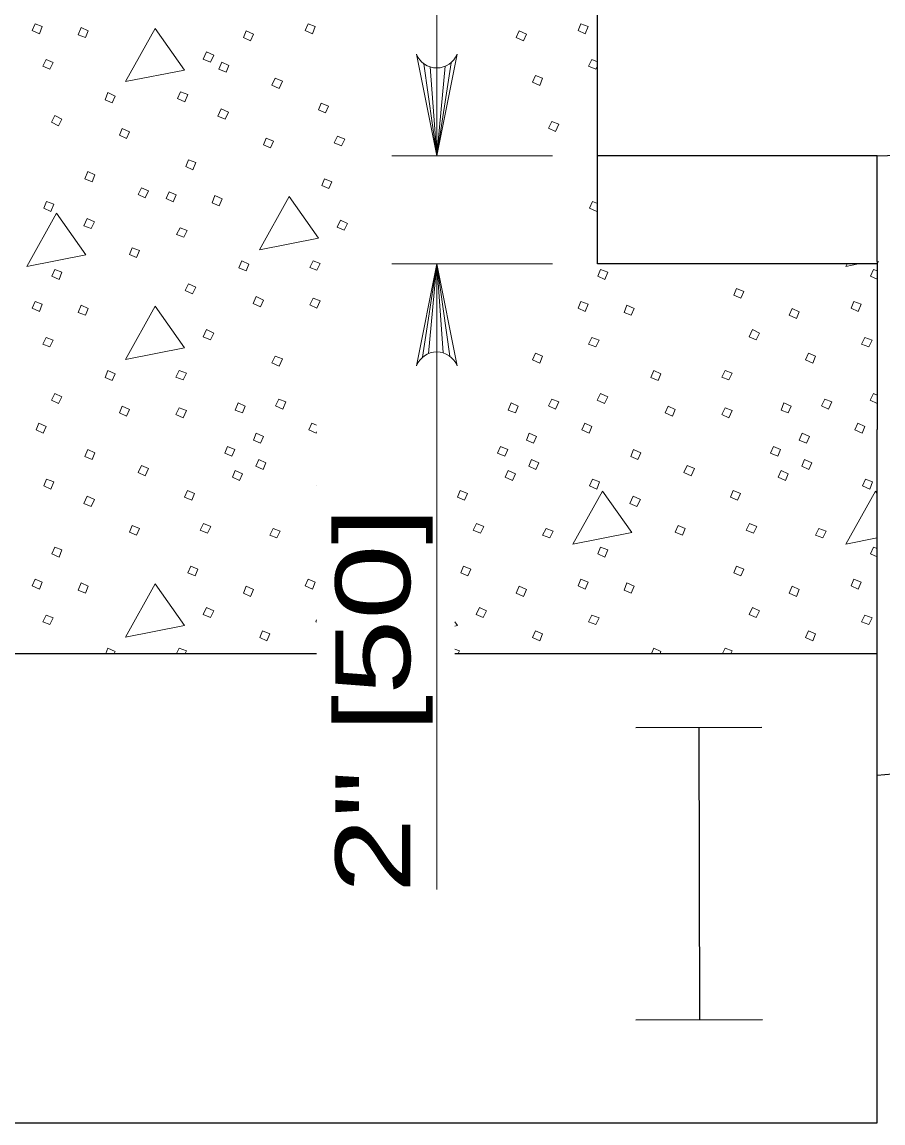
# Model space of a CAD drawing. Extents: x 1083.1 to 1123, y 697.4 to 741.4.
# Drawn here: x 1091.084 to 1092.878, y 711.561 to 713.855 of the extents above; entities that cross this region are included whole.
import ezdxf

# ---------------------------------------------------------------- set-up
doc = ezdxf.new("R2010")
doc.units = 0
doc.header["$LTSCALE"] = 0.062
doc.layers.add('1', color=7, linetype='Continuous', lineweight=13)

msp = doc.modelspace()

# ---------------------------------------------------------------- linework, layer by layer
at = {"layer": '1'}
for p, q in [((1091.94833, 713.92525), (1091.94833, 713.57625)), ((1091.9215, 713.76825), (1091.94833, 713.57625)), ((1091.93475, 713.76175), (1091.94833, 713.57625)), ((1091.978, 713.7705), (1091.94833, 713.57625)), ((1091.96558, 713.76317), (1091.94833, 713.57625)), ((1091.94833, 713.75975), (1091.94833, 713.57625)), ((1092.27175, 713.777), (1092.28325, 713.77242)), ((1092.18967, 713.57625), (1091.85475, 713.57625)), ((1092.27275, 713.48167), (1092.28325, 713.4775)), ((1092.18967, 713.35117), (1091.85475, 713.35117)), ((1091.91867, 713.157), (1091.94833, 713.35117)), ((1091.93108, 713.16433), (1091.94833, 713.35117)), ((1091.94833, 713.16417), (1091.94833, 713.35117)), ((1091.94833, 713.16775), (1091.94833, 713.35117)), ((1091.96192, 713.16575), (1091.94833, 713.35117)), ((1091.97517, 713.15925), (1091.94833, 713.35117)), ((1092.86625, 713.3535), (1092.869, 713.35617)), ((1092.85842, 713.34), (1092.86625, 713.33683)), ((1092.85842, 713.08158), (1092.86625, 713.07792)), ((1091.688, 713.01975), (1091.698, 713.01508)), ((1092.86625, 712.8725), (1092.86242, 712.87808)), ((1092.85842, 712.76133), (1092.86625, 712.75817)), ((1091.25833, 712.53942), (1091.26292, 712.55083)), ((1091.40592, 712.53942), (1091.41158, 712.55083)), ((1092.39583, 712.53942), (1092.40042, 712.55083)), ((1092.54342, 712.53942), (1092.54908, 712.55083))]:
    msp.add_line(p, q, dxfattribs=at)
at = {"layer": '1', "lineweight": 25}
for p, q in [((1092.86625, 713.57625), (1094.211, 713.62042)), ((1092.86625, 713.57625), (1092.28325, 713.57625)), ((1092.86625, 713.356), (1092.86625, 713.57625)), ((1092.86625, 713.356), (1092.86625, 713.0065)), ((1092.86625, 712.53942), (1092.86625, 713.0065)), ((1088.68575, 712.53942), (1091.698, 712.53942)), ((1091.98583, 712.53942), (1092.86625, 712.53942)), ((1092.86625, 711.56133), (1092.86625, 712.53942)), ((1092.86625, 712.28617), (1095.26192, 712.49675)), ((1092.36333, 712.38567), (1092.6255, 712.38633)), ((1092.49442, 712.38608), (1092.496, 711.77658)), ((1092.36333, 711.77625), (1092.62708, 711.777)), ((1088.68575, 711.56133), (1092.86625, 711.56133))]:
    msp.add_line(p, q, dxfattribs=at)
for points in [[(1092.86625, 713.35117), (1092.28325, 713.35117), (1092.28325, 713.89792), (1091.6065, 714.96742), (1091.41967, 716.86658)], [(1092.28325, 713.646), (1092.28267, 713.64633), (1092.28325, 713.6475)]]:
    msp.add_lwpolyline(points, dxfattribs=at)
at = {"layer": '1'}
for points in [[(1091.11133, 713.85183), (1091.12625, 713.84583), (1091.12025, 713.83083), (1091.10533, 713.83783)], [(1091.68, 713.85183), (1091.695, 713.84583), (1091.689, 713.83083), (1091.674, 713.83783)], [(1092.24875, 713.85183), (1092.26375, 713.84583), (1092.25775, 713.83083), (1092.24275, 713.83783)], [(1091.20708, 713.84383), (1091.22208, 713.83683), (1091.21608, 713.82292), (1091.20108, 713.82892)], [(1091.36175, 713.84183), (1091.29983, 713.73108), (1091.42258, 713.75508)], [(1091.55133, 713.83683), (1091.56625, 713.82983), (1091.56033, 713.81592), (1091.54533, 713.82292)], [(1092.12008, 713.83683), (1092.135, 713.82983), (1092.129, 713.81592), (1092.11408, 713.82292)], [(1091.4685, 713.793), (1091.4835, 713.786), (1091.4765, 713.772), (1091.4615, 713.778)], [(1091.13425, 713.777), (1091.14917, 713.771), (1091.14225, 713.75708), (1091.12725, 713.763)], [(1091.50008, 713.772), (1091.51508, 713.765), (1091.50908, 713.751), (1091.49408, 713.757)], [(1091.61183, 713.73808), (1091.62683, 713.73208), (1091.61983, 713.71708), (1091.60483, 713.72408)], [(1092.154, 713.74408), (1092.16892, 713.73808), (1092.16292, 713.72308), (1092.148, 713.73008)], [(1091.41425, 713.71008), (1091.42925, 713.70417), (1091.42325, 713.68917), (1091.40825, 713.69617)], [(1091.26292, 713.70817), (1091.27792, 713.70117), (1091.27192, 713.68717), (1091.257, 713.69317)], [(1091.49908, 713.67417), (1091.51408, 713.66725), (1091.50708, 713.65325), (1091.49208, 713.65925)], [(1091.70758, 713.68617), (1091.72258, 713.68017), (1091.71658, 713.66617), (1091.70167, 713.67217)], [(1091.15217, 713.66025), (1091.16717, 713.65325), (1091.16017, 713.63933), (1091.14525, 713.64633)], [(1092.18792, 713.64833), (1092.20283, 713.64233), (1092.19592, 713.62733), (1092.18092, 713.63433)], [(1091.29292, 713.63333), (1091.30783, 713.62633), (1091.30183, 713.61242), (1091.28692, 713.61933)], [(1091.59283, 713.61333), (1091.60783, 713.60733), (1091.60183, 713.59342), (1091.58692, 713.59933)], [(1091.74158, 713.61733), (1091.7565, 713.61133), (1091.7495, 713.59733), (1091.73458, 713.60333)], [(1091.43125, 713.56842), (1091.44617, 713.56242), (1091.44017, 713.5475), (1091.42525, 713.5545)], [(1091.22108, 713.54358), (1091.236, 713.53658), (1091.23, 713.52258), (1091.21508, 713.52858)], [(1091.71458, 713.5285), (1091.72958, 713.5225), (1091.72358, 713.50858), (1091.70858, 713.51458)], [(1091.33283, 713.50958), (1091.34775, 713.50367), (1091.34075, 713.48867), (1091.32583, 713.49567)], [(1091.13525, 713.48167), (1091.15017, 713.47567), (1091.14425, 713.46075), (1091.12925, 713.46775)], [(1091.39033, 713.50158), (1091.40525, 713.49558), (1091.39933, 713.48067), (1091.38433, 713.48767)], [(1091.48608, 713.49358), (1091.50108, 713.48667), (1091.49508, 713.47267), (1091.48008, 713.47867)], [(1091.64075, 713.49158), (1091.57892, 713.38083), (1091.70167, 713.40483)], [(1091.15617, 713.45675), (1091.09433, 713.346), (1091.21708, 713.36992)], [(1091.22008, 713.44575), (1091.235, 713.43875), (1091.228, 713.42483), (1091.21308, 713.43083)], [(1091.7475, 713.44275), (1091.7625, 713.43575), (1091.7555, 713.42175), (1091.74058, 713.42775)], [(1091.41325, 713.42675), (1091.42825, 713.42075), (1091.42125, 713.40683), (1091.40625, 713.41283)], [(1091.31383, 713.38492), (1091.32883, 713.37892), (1091.32283, 713.36492), (1091.30783, 713.37092)], [(1091.542, 713.35792), (1091.55692, 713.35092), (1091.551, 713.337), (1091.536, 713.343)], [(1091.69067, 713.35792), (1091.70558, 713.35192), (1091.69867, 713.338), (1091.68367, 713.34392)], [(1091.15217, 713.34), (1091.16717, 713.334), (1091.16117, 713.31908), (1091.14625, 713.32608)], [(1092.28967, 713.34), (1092.30467, 713.334), (1092.29867, 713.31908), (1092.28367, 713.32608)], [(1091.43125, 713.31), (1091.44617, 713.30308), (1091.43925, 713.28908), (1091.42425, 713.29608)], [(1092.573, 713.30008), (1092.588, 713.29408), (1092.582, 713.28017), (1092.56708, 713.28617)], [(1091.57192, 713.28308), (1091.58692, 713.27608), (1091.58092, 713.26217), (1091.56592, 713.26917)], [(1091.69067, 713.28008), (1091.70558, 713.27417), (1091.69867, 713.25917), (1091.68367, 713.26617)], [(1091.11133, 713.27317), (1091.12625, 713.26717), (1091.12025, 713.25225), (1091.10533, 713.25917)], [(1091.20708, 713.26517), (1091.22208, 713.25825), (1091.21608, 713.24425), (1091.20108, 713.25025)], [(1091.36175, 713.26317), (1091.29983, 713.15242), (1091.42258, 713.17642)], [(1092.24875, 713.27317), (1092.26375, 713.26717), (1092.25775, 713.25225), (1092.24275, 713.25917)], [(1092.34458, 713.26517), (1092.3595, 713.25825), (1092.3535, 713.24425), (1092.33858, 713.25025)], [(1092.68875, 713.25825), (1092.70375, 713.25125), (1092.69775, 713.23725), (1092.68275, 713.24425)], [(1092.8175, 713.27317), (1092.8325, 713.26717), (1092.8265, 713.25225), (1092.8115, 713.25917)], [(1091.4685, 713.21433), (1091.4835, 713.20733), (1091.4765, 713.19333), (1091.4615, 713.19933)], [(1092.606, 713.21433), (1092.62092, 713.20733), (1092.61392, 713.19333), (1092.599, 713.19933)], [(1091.13425, 713.19833), (1091.14917, 713.19233), (1091.14225, 713.17842), (1091.12725, 713.18442)], [(1092.27175, 713.19833), (1092.28667, 713.19233), (1092.27967, 713.17842), (1092.26475, 713.18442)], [(1092.84042, 713.19833), (1092.85542, 713.19233), (1092.84842, 713.17842), (1092.8335, 713.18442)], [(1091.61183, 713.15942), (1091.62683, 713.15342), (1091.61983, 713.13842), (1091.60483, 713.14542)], [(1092.154, 713.16542), (1092.16892, 713.15942), (1092.16292, 713.1445), (1092.148, 713.1515)], [(1092.72267, 713.16542), (1092.73767, 713.15942), (1092.73167, 713.1445), (1092.71675, 713.1515)], [(1091.26292, 713.1295), (1091.27792, 713.1225), (1091.27192, 713.10858), (1091.257, 713.11458)], [(1091.41158, 713.1295), (1091.42658, 713.1235), (1091.41958, 713.10958), (1091.40467, 713.1155)], [(1092.40042, 713.1295), (1092.41542, 713.1225), (1092.40942, 713.10858), (1092.39442, 713.11458)], [(1092.54908, 713.1295), (1092.56408, 713.1235), (1092.55708, 713.10958), (1092.54208, 713.1155)], [(1091.15217, 713.08158), (1091.16717, 713.07467), (1091.16017, 713.06067), (1091.14525, 713.06767)], [(1091.61917, 713.06967), (1091.63408, 713.06367), (1091.62717, 713.04867), (1091.61217, 713.05567)], [(1092.18792, 713.06967), (1092.20283, 713.06367), (1092.19592, 713.04867), (1092.18092, 713.05567)], [(1092.28967, 713.08158), (1092.30467, 713.07467), (1092.29767, 713.06067), (1092.28267, 713.06767)], [(1092.75667, 713.06967), (1092.77158, 713.06367), (1092.76458, 713.04867), (1092.74967, 713.05567)], [(1091.29292, 713.05467), (1091.30783, 713.04767), (1091.30183, 713.03375), (1091.28692, 713.04075)], [(1091.41158, 713.05167), (1091.42658, 713.04567), (1091.41958, 713.03075), (1091.40467, 713.03775)], [(1091.53433, 713.06167), (1091.54933, 713.05467), (1091.54333, 713.04075), (1091.52833, 713.04667)], [(1092.10308, 713.06167), (1092.11808, 713.05467), (1092.11208, 713.04075), (1092.09708, 713.04667)], [(1092.43033, 713.05467), (1092.44533, 713.04767), (1092.43933, 713.03375), (1092.42433, 713.04075)], [(1092.54908, 713.05167), (1092.56408, 713.04567), (1092.55708, 713.03075), (1092.54208, 713.03775)], [(1092.67183, 713.06167), (1092.68675, 713.05467), (1092.68083, 713.04075), (1092.66583, 713.04667)], [(1091.11925, 713.01975), (1091.13425, 713.01275), (1091.12825, 712.99883), (1091.11325, 713.00583)], [(1091.57225, 712.99883), (1091.58725, 712.99183), (1091.58125, 712.97783), (1091.56625, 712.98383)], [(1092.141, 712.99883), (1092.156, 712.99183), (1092.15, 712.97783), (1092.135, 712.98383)], [(1092.25675, 713.01975), (1092.27175, 713.01275), (1092.26575, 712.99883), (1092.25075, 713.00583)], [(1092.70975, 712.99883), (1092.72467, 712.99183), (1092.71875, 712.97783), (1092.70375, 712.98383)], [(1092.8255, 713.01975), (1092.84042, 713.01275), (1092.83442, 712.99883), (1092.8195, 713.00583)], [(1091.22108, 712.96492), (1091.236, 712.95792), (1091.23, 712.94392), (1091.21508, 712.94992)], [(1091.51242, 712.97083), (1091.52733, 712.96492), (1091.52142, 712.95092), (1091.50642, 712.95692)], [(1092.08117, 712.97083), (1092.09608, 712.96492), (1092.09008, 712.95092), (1092.07517, 712.95692)], [(1092.3585, 712.96492), (1092.3735, 712.95792), (1092.3675, 712.94392), (1092.3525, 712.94992)], [(1092.64983, 712.97083), (1092.66483, 712.96492), (1092.65883, 712.95092), (1092.64392, 712.95692)], [(1091.33283, 712.931), (1091.34775, 712.925), (1091.34075, 712.91), (1091.32583, 712.917)], [(1091.57725, 712.94392), (1091.59225, 712.937), (1091.58625, 712.923), (1091.57125, 712.93)], [(1092.146, 712.94392), (1092.161, 712.937), (1092.155, 712.923), (1092.14, 712.93)], [(1092.47025, 712.931), (1092.48525, 712.925), (1092.47825, 712.91), (1092.46325, 712.917)], [(1092.71475, 712.94392), (1092.72967, 712.937), (1092.72375, 712.923), (1092.70875, 712.93)], [(1091.52833, 712.921), (1091.54333, 712.914), (1091.53733, 712.90008), (1091.52242, 712.907)], [(1092.09708, 712.921), (1092.11208, 712.914), (1092.10608, 712.90008), (1092.09108, 712.907)], [(1092.66583, 712.921), (1092.68083, 712.914), (1092.67483, 712.90008), (1092.65983, 712.907)], [(1091.13525, 712.903), (1091.15017, 712.89708), (1091.14425, 712.88208), (1091.12925, 712.88908)], [(1092.27275, 712.903), (1092.28767, 712.89708), (1092.28167, 712.88208), (1092.26675, 712.88908)], [(1092.84142, 712.903), (1092.85642, 712.89708), (1092.85042, 712.88208), (1092.83542, 712.88908)], [(1091.22008, 712.86708), (1091.235, 712.86017), (1091.228, 712.84617), (1091.21308, 712.85217)], [(1091.42858, 712.87908), (1091.44358, 712.87308), (1091.43758, 712.85917), (1091.42258, 712.86508)], [(1091.99733, 712.87908), (1092.01225, 712.87308), (1092.00633, 712.85917), (1091.99133, 712.86508)], [(1092.29367, 712.87808), (1092.23183, 712.76733), (1092.3545, 712.79133)], [(1092.3575, 712.86708), (1092.3725, 712.86017), (1092.3655, 712.84617), (1092.3505, 712.85217)], [(1092.56608, 712.87908), (1092.581, 712.87308), (1092.575, 712.85917), (1092.56008, 712.86508)], [(1091.31383, 712.80625), (1091.32883, 712.80025), (1091.32283, 712.78633), (1091.30783, 712.79233)], [(1091.4625, 712.81025), (1091.4775, 712.80425), (1091.4705, 712.79033), (1091.4555, 712.79625)], [(1091.60717, 712.80025), (1091.62217, 712.79425), (1091.61517, 712.78033), (1091.60017, 712.78633)], [(1092.03125, 712.81025), (1092.04625, 712.80425), (1092.03925, 712.79033), (1092.02425, 712.79625)], [(1092.17592, 712.80025), (1092.19092, 712.79425), (1092.18392, 712.78033), (1092.16892, 712.78633)], [(1092.45133, 712.80625), (1092.46625, 712.80025), (1092.46025, 712.78633), (1092.44533, 712.79233)], [(1092.6, 712.81025), (1092.61492, 712.80425), (1092.608, 712.79033), (1092.593, 712.79625)], [(1092.74467, 712.80025), (1092.75967, 712.79425), (1092.75267, 712.78033), (1092.73767, 712.78633)], [(1091.15217, 712.76133), (1091.16717, 712.75542), (1091.16117, 712.74042), (1091.14625, 712.74742)], [(1092.28967, 712.76133), (1092.30467, 712.75542), (1092.29867, 712.74042), (1092.28367, 712.74742)], [(1091.43558, 712.7215), (1091.4505, 712.7155), (1091.44458, 712.7015), (1091.42958, 712.7075)], [(1092.00433, 712.7215), (1092.01925, 712.7155), (1092.01325, 712.7015), (1091.99833, 712.7075)], [(1092.573, 712.7215), (1092.588, 712.7155), (1092.582, 712.7015), (1092.56708, 712.7075)], [(1091.11133, 712.6945), (1091.12625, 712.6885), (1091.12025, 712.67358), (1091.10533, 712.68058)], [(1091.20708, 712.6865), (1091.22208, 712.67958), (1091.21608, 712.66558), (1091.20108, 712.67158)], [(1091.36175, 712.68458), (1091.29983, 712.57383), (1091.42258, 712.59775)], [(1091.55133, 712.67958), (1091.56625, 712.67258), (1091.56033, 712.65858), (1091.54533, 712.66558)], [(1091.68, 712.6945), (1091.695, 712.6885), (1091.689, 712.67358), (1091.674, 712.68058)], [(1092.12008, 712.67958), (1092.135, 712.67258), (1092.129, 712.65858), (1092.11408, 712.66558)], [(1092.24875, 712.6945), (1092.26375, 712.6885), (1092.25775, 712.67358), (1092.24275, 712.68058)], [(1092.34458, 712.6865), (1092.3595, 712.67958), (1092.3535, 712.66558), (1092.33858, 712.67158)], [(1092.68875, 712.67958), (1092.70375, 712.67258), (1092.69775, 712.65858), (1092.68275, 712.66558)], [(1092.8175, 712.6945), (1092.8325, 712.6885), (1092.8265, 712.67358), (1092.8115, 712.68058)], [(1091.4685, 712.63567), (1091.4835, 712.62867), (1091.4765, 712.61475), (1091.4615, 712.62067)], [(1092.03725, 712.63567), (1092.05217, 712.62867), (1092.04525, 712.61475), (1092.03025, 712.62067)], [(1092.606, 712.63567), (1092.62092, 712.62867), (1092.61392, 712.61475), (1092.599, 712.62067)], [(1091.13425, 712.61967), (1091.14917, 712.61375), (1091.14225, 712.59975), (1091.12725, 712.60575)], [(1092.27175, 712.61967), (1092.28667, 712.61375), (1092.27967, 712.59975), (1092.26475, 712.60575)], [(1092.84042, 712.61967), (1092.85542, 712.61375), (1092.84842, 712.59975), (1092.8335, 712.60575)], [(1091.58525, 712.58675), (1091.60017, 712.58075), (1091.59425, 712.56583), (1091.57925, 712.57283)], [(1092.154, 712.58675), (1092.16892, 712.58075), (1092.16292, 712.56583), (1092.148, 712.57283)], [(1092.72267, 712.58675), (1092.73767, 712.58075), (1092.73167, 712.56583), (1092.71675, 712.57283)]]:
    msp.add_lwpolyline(points, close=True, dxfattribs=at)
for points in [[(1091.99075, 713.78833), (1091.94833, 713.57625), (1091.90592, 713.78833)], [(1092.28325, 713.76425), (1092.27967, 713.75708), (1092.26475, 713.763), (1092.27175, 713.777)], [(1092.28325, 713.46475), (1092.28167, 713.46075), (1092.26675, 713.46775), (1092.27275, 713.48167)], [(1091.90592, 713.13917), (1091.94833, 713.35117), (1091.99075, 713.13917)], [(1091.94833, 713.35117), (1091.94833, 712.46317), (1091.94833, 712.04783)], [(1092.80342, 713.35117), (1092.8005, 713.346), (1092.82708, 713.35117)], [(1092.86625, 713.31958), (1092.85242, 713.32608), (1092.85842, 713.34)], [(1092.86625, 713.06067), (1092.85142, 713.06767), (1092.85842, 713.08158)], [(1091.698, 713.00125), (1091.697, 712.99883), (1091.682, 713.00583), (1091.688, 713.01975)], [(1091.698, 712.889), (1091.698, 712.88908), (1091.698, 712.88917)], [(1092.86242, 712.87808), (1092.8005, 712.76733), (1092.86625, 712.78025)], [(1092.86625, 712.74092), (1092.85242, 712.74742), (1092.85842, 712.76133)], [(1091.698, 712.60492), (1091.696, 712.60575), (1091.698, 712.60983)], [(1091.98583, 712.59667), (1091.99133, 712.59775), (1091.98583, 712.60558)], [(1091.26292, 712.55083), (1091.27792, 712.54392), (1091.276, 712.53942)], [(1091.41158, 712.55083), (1091.42658, 712.54483), (1091.42392, 712.53942)], [(1091.98583, 712.54867), (1091.99533, 712.54483), (1091.99267, 712.53942)], [(1092.40042, 712.55083), (1092.41542, 712.54392), (1092.4135, 712.53942)], [(1092.54908, 712.55083), (1092.56408, 712.54483), (1092.56133, 712.53942)]]:
    msp.add_lwpolyline(points, dxfattribs=at)
for centre, start, end in [((1091.94828, 713.80542), 202.08782, 337.91395), ((1091.94837, 713.12204), 22.08782, 157.91395)]:
    msp.add_arc(centre, 0.04576, start, end, dxfattribs=at)

# ---------------------------------------------------------------- texts
at = {"layer": '1', "width": 1.35}
msp.add_text('2" [50]', height=0.156, rotation=90, dxfattribs=at).set_placement((1091.89292, 712.04033))

doc.saveas('drawing.dxf')
